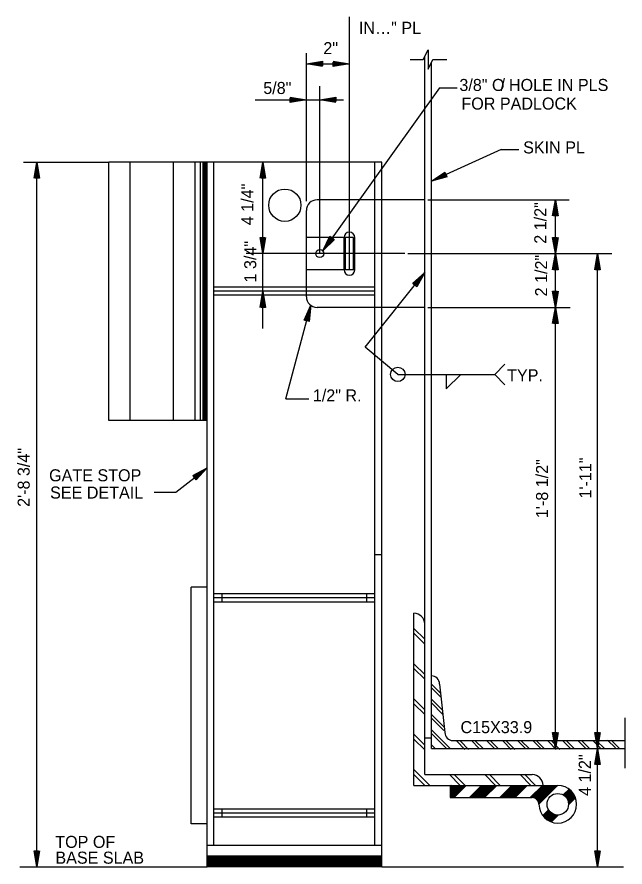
# Model space of a CAD drawing. Extents: x 0.1 to 13.5, y 0.1 to 9.5.
# Drawn here: x 6.55 to 8.905, y 3.832 to 7.124 of the extents above; entities that cross this region are included whole.
import ezdxf

# ---------------------------------------------------------------- set-up
doc = ezdxf.new("R2010")
doc.units = 0
for name, color, linetype in [('Level 13', 7, 'Continuous'), ('Level 25', 7, 'Continuous'), ('Level 36', 7, 'Continuous'), ('Level 44', 7, 'Continuous'), ('Level 50', 7, 'Continuous')]:
    doc.layers.add(name, color=color, linetype=linetype)

msp = doc.modelspace()

# ---------------------------------------------------------------- linework, layer by layer
at = {"layer": 'Level 13'}
for p, q in [((8.2281, 4.1483), (8.2281, 4.1014)), ((8.2281, 4.1483), (8.6448, 4.1483)), ((8.2685, 4.1483), (8.2281, 4.1079)), ((8.2611, 4.1483), (8.2281, 4.1153)), ((8.2537, 4.1483), (8.2281, 4.1226)), ((8.2464, 4.1483), (8.2281, 4.13)), ((8.239, 4.1483), (8.2281, 4.1374)), ((8.2353, 4.1483), (8.2281, 4.1411)), ((8.2427, 4.1483), (8.2281, 4.1337)), ((8.2316, 4.1483), (8.2281, 4.1448)), ((8.2501, 4.1483), (8.2281, 4.1263)), ((8.2574, 4.1483), (8.2281, 4.119)), ((8.2648, 4.1483), (8.2281, 4.1116)), ((8.2722, 4.1483), (8.2281, 4.1042)), ((8.2758, 4.1483), (8.229, 4.1014)), ((8.2795, 4.1483), (8.2327, 4.1014)), ((8.2832, 4.1483), (8.2363, 4.1014)), ((8.2869, 4.1483), (8.24, 4.1014)), ((8.2906, 4.1483), (8.2437, 4.1014)), ((8.3495, 4.1483), (8.3026, 4.1014)), ((8.3532, 4.1483), (8.3063, 4.1014)), ((8.3568, 4.1483), (8.31, 4.1014)), ((8.3605, 4.1483), (8.3137, 4.1014)), ((8.3642, 4.1483), (8.3173, 4.1014)), ((8.3679, 4.1483), (8.321, 4.1014)), ((8.3716, 4.1483), (8.3247, 4.1014)), ((8.3753, 4.1483), (8.3284, 4.1014)), ((8.3789, 4.1483), (8.3321, 4.1014)), ((8.3826, 4.1483), (8.3357, 4.1014)), ((8.3863, 4.1483), (8.3394, 4.1014)), ((8.39, 4.1483), (8.3431, 4.1014)), ((8.3937, 4.1483), (8.3468, 4.1014)), ((8.3973, 4.1483), (8.3505, 4.1014)), ((8.401, 4.1483), (8.3542, 4.1014)), ((8.4047, 4.1483), (8.3578, 4.1014)), ((8.4084, 4.1483), (8.3615, 4.1014)), ((8.4673, 4.1483), (8.4205, 4.1014)), ((8.471, 4.1483), (8.4241, 4.1014)), ((8.4747, 4.1483), (8.4278, 4.1014)), ((8.4784, 4.1483), (8.4315, 4.1014)), ((8.4821, 4.1483), (8.4352, 4.1014)), ((8.4857, 4.1483), (8.4389, 4.1014)), ((8.4894, 4.1483), (8.4426, 4.1014)), ((8.4931, 4.1483), (8.4462, 4.1014)), ((8.4968, 4.1483), (8.4499, 4.1014)), ((8.5005, 4.1483), (8.4536, 4.1014)), ((8.5042, 4.1483), (8.4573, 4.1014)), ((8.5078, 4.1483), (8.461, 4.1014)), ((8.5115, 4.1483), (8.4647, 4.1014)), ((8.5152, 4.1483), (8.4683, 4.1014)), ((8.5115, 4.1483), (8.4683, 4.1051)), ((8.5189, 4.1483), (8.472, 4.1014)), ((8.5226, 4.1483), (8.4757, 4.1014)), ((8.5263, 4.1483), (8.4794, 4.1014)), ((8.5852, 4.1483), (8.5383, 4.1014)), ((8.5889, 4.1483), (8.542, 4.1014)), ((8.5925, 4.1483), (8.5457, 4.1014)), ((8.5962, 4.1483), (8.5491, 4.1012)), ((8.5999, 4.1483), (8.5523, 4.1006)), ((8.6036, 4.1483), (8.5551, 4.0997)), ((8.6073, 4.1483), (8.5576, 4.0986)), ((8.611, 4.1483), (8.5599, 4.0972)), ((8.6146, 4.1483), (8.5621, 4.0957)), ((8.6183, 4.1483), (8.5639, 4.0939)), ((8.622, 4.1483), (8.5658, 4.0921)), ((8.6257, 4.1483), (8.5677, 4.0902)), ((8.6294, 4.1483), (8.5688, 4.0877)), ((8.6331, 4.1483), (8.57, 4.0852)), ((8.6367, 4.1483), (8.5709, 4.0824)), ((8.6404, 4.1483), (8.5716, 4.0794)), ((8.6441, 4.1483), (8.5719, 4.076)), ((8.6885, 4.1337), (8.666, 4.1112)), ((8.6906, 4.1321), (8.6683, 4.1098)), ((8.6926, 4.1304), (8.6704, 4.1082)), ((8.6944, 4.1286), (8.6724, 4.1066)), ((8.6964, 4.1269), (8.6743, 4.1048)), ((8.6982, 4.125), (8.6761, 4.1029)), ((8.6999, 4.1231), (8.6777, 4.1009)), ((8.7016, 4.1211), (8.6796, 4.099)), ((8.7032, 4.119), (8.6807, 4.0965)), ((8.7048, 4.1168), (8.682, 4.0941)), ((8.7062, 4.1146), (8.6832, 4.0916)), ((8.2281, 4.1014), (8.5458, 4.1014)), ((8.7076, 4.1124), (8.6842, 4.0889)), ((8.709, 4.11), (8.6851, 4.0861)), ((8.7102, 4.1076), (8.6858, 4.0831)), ((8.7114, 4.1051), (8.6862, 4.0799)), ((8.7135, 4.0998), (8.6864, 4.0727)), ((8.7125, 4.1025), (8.6865, 4.0765)), ((8.6089, 4.0542), (8.5864, 4.0317)), ((8.6104, 4.0519), (8.5883, 4.0298)), ((8.6119, 4.0498), (8.5897, 4.0276)), ((8.6136, 4.0478), (8.5916, 4.0257)), ((8.6154, 4.0459), (8.5933, 4.0238)), ((8.6172, 4.044), (8.5951, 4.0219)), ((8.6193, 4.0424), (8.5971, 4.0202)), ((8.6214, 4.0409), (8.5991, 4.0185)), ((8.6237, 4.0394), (8.6012, 4.0169)), ((8.6261, 4.0381), (8.6033, 4.0154)), ((8.6286, 4.037), (8.6055, 4.0139)), ((8.6312, 4.0359), (8.6078, 4.0125)), ((8.634, 4.0351), (8.6101, 4.0112)), ((8.637, 4.0344), (8.6126, 4.0099)), ((8.6402, 4.0339), (8.6151, 4.0088)), ((8.6437, 4.0337), (8.6177, 4.0077)), ((8.6474, 4.0338), (8.6203, 4.0066))]:
    msp.add_line(p, q, dxfattribs=at)
msp.add_lwpolyline([(8.124, 6.9584), (8.1426, 6.9959), (8.1426, 6.921), (8.1614, 6.9584)], dxfattribs=at)
msp.add_circle((8.6448, 4.0753), 0.0417, dxfattribs=at)
for centre, radius, start in [((8.6448, 4.0753), 0.0729, 180), ((8.5459, 4.0753), 0.026, 0)]:
    msp.add_arc(centre, radius, start, 90, dxfattribs=at)
at = {"layer": 'Level 25'}
for p, q in [((7.8377, 6.1449), (7.8377, 7.1236)), ((7.6711, 6.4099), (7.6711, 6.9833)), ((8.0737, 6.9584), (8.124, 6.9584)), ((8.1294, 4.1899), (8.1294, 6.9692)), ((8.1554, 4.3326), (8.1554, 6.9465)), ((8.1614, 6.9584), (8.2147, 6.9584)), ((7.6711, 6.9417), (7.8377, 6.9417)), ((7.7231, 6.2074), (7.7231, 6.8564)), ((8.187, 6.8498), (7.7347, 6.2179)), ((8.187, 6.8498), (8.2546, 6.8498)), ((7.4724, 6.8035), (7.6711, 6.8035)), ((7.6711, 6.8035), (7.7231, 6.8035)), ((7.7231, 6.8035), (7.815, 6.8035)), ((8.4259, 6.6108), (8.4935, 6.6108)), ((6.5752, 6.5615), (6.9054, 6.5615)), ((6.6265, 3.8324), (6.6265, 6.5615)), ((7.9627, 6.5615), (6.9054, 6.5615)), ((6.9054, 5.5615), (6.9054, 6.5615)), ((6.9888, 5.5615), (6.9888, 6.5615)), ((7.1567, 5.5615), (7.1567, 6.5615)), ((7.24, 5.5615), (7.24, 6.5615)), ((7.2608, 5.5615), (7.2608, 6.5615)), ((7.2713, 5.5615), (7.2713, 6.5615)), ((7.2765, 5.5615), (7.2765, 6.5615)), ((7.2817, 5.5615), (7.2817, 6.5615)), ((7.2869, 3.8324), (7.2869, 6.5615)), ((7.3131, 3.9157), (7.3131, 6.5615)), ((7.5028, 6.2074), (7.5028, 6.5615)), ((7.9365, 6.4157), (7.9365, 6.5615)), ((7.9627, 6.5615), (7.9627, 6.5615)), ((7.9627, 6.4157), (7.9627, 6.5615)), ((8.1294, 6.4157), (7.7127, 6.4157)), ((7.9365, 5.999), (7.9365, 6.4157)), ((7.9627, 5.999), (7.9627, 6.4157)), ((8.1413, 6.4157), (8.6889, 6.4157)), ((8.6354, 6.2074), (8.6354, 6.4157)), ((7.6711, 6.0407), (7.6711, 6.374)), ((7.8533, 6.2699), (7.6711, 6.2699)), ((7.8169, 6.1449), (7.8169, 6.2699)), ((7.8221, 6.1449), (7.8221, 6.2699)), ((7.8533, 6.1449), (7.8533, 6.2699)), ((7.8586, 6.1449), (7.8586, 6.2699)), ((8.0528, 6.2074), (7.4375, 6.2074)), ((7.5028, 6.0615), (7.5028, 6.2074)), ((8.0644, 6.2074), (8.8544, 6.2074)), ((8.6354, 5.999), (8.6354, 6.2074)), ((8.7985, 4.2909), (8.7985, 6.2074)), ((7.8533, 6.1449), (7.6711, 6.1449)), ((7.8993, 5.8454), (8.1294, 6.1346)), ((7.6711, 6.0771), (7.3131, 6.0771)), ((7.9365, 6.0615), (7.3131, 6.0615)), ((7.5028, 5.9169), (7.5028, 6.0615)), ((7.9365, 6.0771), (7.6711, 6.0771)), ((7.6711, 6.0459), (7.3131, 6.0459)), ((7.9365, 6.0459), (7.6711, 6.0459)), ((7.5917, 5.6446), (7.6879, 6.0072)), ((8.1294, 5.999), (7.7127, 5.999)), ((7.9365, 3.9157), (7.9365, 5.999)), ((7.9627, 3.8324), (7.9627, 5.999)), ((8.1413, 5.999), (8.6933, 5.999)), ((8.6354, 4.2909), (8.6354, 5.999)), ((8.0253, 5.7397), (7.8993, 5.8454)), ((8.4004, 5.7397), (8.4403, 5.7795)), ((8.0253, 5.7397), (8.4004, 5.7397)), ((8.2128, 5.7397), (8.2128, 5.6834)), ((8.2128, 5.6834), (8.2687, 5.7393)), ((8.4004, 5.7397), (8.4403, 5.6999)), ((7.5917, 5.6446), (7.6801, 5.6446)), ((7.2869, 5.5615), (6.9054, 5.5615)), ((7.1657, 5.2836), (7.2869, 5.3783)), ((7.081, 5.2836), (7.1657, 5.2836)), ((7.9627, 5.0407), (7.9365, 5.0407)), ((7.2244, 3.999), (7.2244, 4.9157)), ((7.2869, 4.9157), (7.2244, 4.9157)), ((7.9365, 4.8896), (7.3131, 4.8896)), ((7.9365, 4.874), (7.3131, 4.874)), ((7.9365, 4.874), (7.3131, 4.874)), ((7.3444, 4.8584), (7.3444, 4.8896)), ((7.9052, 4.8584), (7.9052, 4.8896)), ((7.9365, 4.8584), (7.3131, 4.8584)), ((8.0877, 4.1483), (8.0877, 4.8149)), ((8.1554, 4.2909), (8.1554, 4.5721)), ((8.1906, 4.5053), (8.1554, 4.5405)), ((8.1924, 4.4896), (8.1554, 4.5266)), ((8.1867, 4.5409), (8.2075, 4.3534)), ((8.198, 4.439), (8.1554, 4.4816)), ((8.1997, 4.4234), (8.1554, 4.4677)), ((8.2029, 4.3751), (8.1554, 4.4226)), ((8.9052, 4.2153), (8.9052, 4.4104)), ((8.2029, 4.3613), (8.1554, 4.4088)), ((8.2282, 4.2909), (8.1554, 4.3637)), ((8.2144, 4.2909), (8.1554, 4.3498)), ((8.1294, 4.3326), (8.1554, 4.3326)), ((8.2388, 4.3221), (8.9052, 4.3221)), ((8.2853, 4.2879), (8.2541, 4.3192)), ((8.2992, 4.2879), (8.268, 4.3192)), ((8.3409, 4.2913), (8.31, 4.3221)), ((8.3552, 4.2909), (8.3249, 4.3212)), ((8.3998, 4.2913), (8.3702, 4.3209)), ((8.4137, 4.2913), (8.3828, 4.3221)), ((8.4641, 4.2879), (8.4328, 4.3192)), ((8.478, 4.2879), (8.4467, 4.3192)), ((8.5196, 4.2913), (8.4888, 4.3221)), ((8.5339, 4.2909), (8.5036, 4.3212)), ((8.5786, 4.2913), (8.549, 4.3209)), ((8.5924, 4.2913), (8.5616, 4.3221)), ((8.6389, 4.2879), (8.6076, 4.3192)), ((8.6527, 4.2879), (8.6215, 4.3192)), ((8.6944, 4.2913), (8.6635, 4.3221)), ((8.7087, 4.2909), (8.6784, 4.3212)), ((8.7533, 4.2913), (8.7238, 4.3209)), ((8.7672, 4.2913), (8.7364, 4.3221)), ((8.8126, 4.2899), (8.7814, 4.3212)), ((8.8265, 4.2899), (8.7953, 4.3212)), ((8.8682, 4.2933), (8.8373, 4.3241)), ((8.8824, 4.2929), (8.8522, 4.3232)), ((8.1693, 4.2909), (8.1554, 4.3048)), ((8.1554, 4.2909), (8.1554, 4.2909)), ((8.1554, 4.2909), (8.696, 4.2909)), ((8.1554, 4.2909), (8.9052, 4.2909)), ((8.7985, 3.8324), (8.7985, 4.2909)), ((8.1294, 4.1899), (8.5461, 4.1899)), ((8.0877, 4.1483), (8.2281, 4.1483)), ((7.9365, 4.0563), (7.3131, 4.0563)), ((7.3444, 4.0251), (7.3444, 4.0563)), ((7.9052, 4.0251), (7.9052, 4.0563)), ((7.9365, 4.0407), (7.3131, 4.0407)), ((7.9365, 4.0251), (7.3131, 4.0251)), ((7.2869, 3.999), (7.2244, 3.999)), ((7.9627, 3.9157), (7.2869, 3.9157)), ((7.9627, 3.874), (7.2869, 3.874)), ((7.9627, 3.8688), (7.2869, 3.8688)), ((7.9627, 3.8636), (7.2869, 3.8636)), ((7.9627, 3.8584), (7.2869, 3.8584)), ((7.9627, 3.8532), (7.2869, 3.8532)), ((6.5612, 3.8324), (7.2869, 3.8324)), ((7.9627, 3.848), (7.2869, 3.848)), ((7.9627, 3.8428), (7.2869, 3.8428)), ((7.9627, 3.8376), (7.2869, 3.8376)), ((7.9627, 3.8324), (7.2869, 3.8324)), ((7.9627, 3.8324), (8.8996, 3.8324))]:
    msp.add_line(p, q, dxfattribs=at)
for centre, radius in [((7.5877, 6.3949), 0.0625), ((7.7231, 6.2074), 0.0156), ((8.0253, 5.7397), 0.0281)]:
    msp.add_circle(centre, radius, dxfattribs=at)
for centre, radius, start, end in [((7.7127, 6.374), 0.0417, 90, 180), ((7.8377, 6.2699), 0.0208, 0, 180), ((7.8377, 6.1449), 0.0208, 180, 357.4819), ((7.7127, 6.0407), 0.0417, 180, 270), ((8.0877, 4.7733), 0.0417, 0, 90), ((8.1554, 4.5409), 0.0313, 0, 90), ((8.2388, 4.3534), 0.0313, 180, 270), ((8.5461, 4.1483), 0.0417, 0, 90)]:
    msp.add_arc(centre, radius, start, end, dxfattribs=at)
at = {"layer": 'Level 36'}
msp.add_line((8.1554, 4.2909), (8.1554, 4.9155), dxfattribs=at)
at = {"layer": 'Level 44'}
for p, q in [((8.4259, 6.6108), (8.1554, 6.4877)), ((8.1294, 4.7146), (8.0877, 4.7563)), ((8.1294, 4.6958), (8.0877, 4.7374)), ((8.1294, 4.5779), (8.0877, 4.6196)), ((8.1294, 4.5591), (8.0877, 4.6007)), ((8.1294, 4.4412), (8.0877, 4.4829)), ((8.1294, 4.4224), (8.0877, 4.464)), ((8.1294, 4.3045), (8.0877, 4.3462)), ((8.1294, 4.2857), (8.0877, 4.3273)), ((8.1489, 4.1483), (8.0877, 4.2095)), ((8.1301, 4.1483), (8.0877, 4.1906)), ((8.2668, 4.1483), (8.2251, 4.1899)), ((8.2856, 4.1483), (8.244, 4.1899)), ((8.4035, 4.1483), (8.3618, 4.1899)), ((8.4223, 4.1483), (8.3807, 4.1899)), ((8.5402, 4.1483), (8.4985, 4.1899)), ((8.5591, 4.1483), (8.5174, 4.1899))]:
    msp.add_line(p, q, dxfattribs=at)
at = {"layer": 'Level 50'}
for p, q in [((7.6711, 6.9417), (7.6711, 6.9417)), ((7.6884, 6.9417), (7.6884, 6.9417)), ((7.8204, 6.9417), (7.8204, 6.9417)), ((7.8377, 6.9417), (7.8377, 6.9417)), ((7.6537, 6.8035), (7.6537, 6.8035)), ((7.6711, 6.8035), (7.6711, 6.8035)), ((7.7231, 6.8035), (7.7231, 6.8035)), ((7.7405, 6.8035), (7.7405, 6.8035)), ((6.6265, 6.5615), (6.6265, 6.5615)), ((7.5028, 6.5615), (7.5028, 6.5615)), ((6.6265, 6.5442), (6.6265, 6.5442)), ((7.5028, 6.5442), (7.5028, 6.5442)), ((8.1554, 6.4877), (8.1554, 6.4877)), ((8.1712, 6.4949), (8.1712, 6.4949)), ((8.6354, 6.4157), (8.6354, 6.4157)), ((8.6354, 6.3984), (8.6354, 6.3984)), ((7.5028, 6.2247), (7.5028, 6.2247)), ((7.7448, 6.232), (7.7448, 6.232)), ((8.6354, 6.2247), (8.6354, 6.2247)), ((7.5028, 6.2074), (7.5028, 6.2074)), ((7.7347, 6.2179), (7.7347, 6.2179)), ((8.6354, 6.2074), (8.6354, 6.2074)), ((8.6354, 6.2074), (8.6354, 6.2074)), ((8.6354, 6.2074), (8.6354, 6.2074)), ((8.6354, 6.19), (8.6354, 6.19)), ((8.6354, 6.19), (8.6354, 6.19)), ((8.7985, 6.2074), (8.7985, 6.2074)), ((8.7985, 6.19), (8.7985, 6.19)), ((8.1294, 6.1346), (8.1294, 6.1346)), ((8.1186, 6.121), (8.1186, 6.121)), ((7.5028, 6.0615), (7.5028, 6.0615)), ((7.5028, 6.0442), (7.5028, 6.0442)), ((7.6835, 5.9904), (7.6835, 5.9904)), ((7.6879, 6.0072), (7.6879, 6.0072)), ((8.6354, 6.0164), (8.6354, 6.0164)), ((8.6354, 5.999), (8.6354, 5.999)), ((8.6354, 5.999), (8.6354, 5.999)), ((8.6354, 5.9817), (8.6354, 5.9817)), ((7.2732, 5.3677), (7.2732, 5.3677)), ((7.2869, 5.3783), (7.2869, 5.3783)), ((8.6354, 4.3082), (8.6354, 4.3082)), ((8.6354, 4.2909), (8.6354, 4.2909)), ((8.7985, 4.3082), (8.7985, 4.3082)), ((8.7985, 4.2909), (8.7985, 4.2909)), ((8.7985, 4.2909), (8.7985, 4.2909)), ((8.7985, 4.2736), (8.7985, 4.2736)), ((6.6265, 3.8497), (6.6265, 3.8497)), ((6.6265, 3.8324), (6.6265, 3.8324)), ((8.7985, 3.8497), (8.7985, 3.8497)), ((8.7985, 3.8324), (8.7985, 3.8324))]:
    msp.add_line(p, q, dxfattribs=at)
for points in [[(7.7334, 6.9314), (7.6711, 6.9417), (7.7334, 6.9521), (7.7334, 6.9344), (7.6884, 6.9417), (7.7307, 6.9487), (7.7307, 6.9374), (7.7051, 6.9417), (7.7281, 6.9454), (7.7281, 6.9407), (7.7224, 6.9417)], [(7.7754, 6.9521), (7.8377, 6.9417), (7.7754, 6.9314), (7.7754, 6.9491), (7.8204, 6.9417), (7.7781, 6.9347), (7.7781, 6.9461), (7.8037, 6.9417), (7.7807, 6.9381), (7.7807, 6.9427), (7.7864, 6.9417)], [(7.6087, 6.8138), (7.6711, 6.8035), (7.6087, 6.7931), (7.6087, 6.8108), (7.6537, 6.8035), (7.6114, 6.7965), (7.6114, 6.8078), (7.6371, 6.8035), (7.6141, 6.7998), (7.6141, 6.8045), (7.6197, 6.8035)], [(7.7855, 6.7931), (7.7231, 6.8035), (7.7855, 6.8138), (7.7855, 6.7961), (7.7405, 6.8035), (7.7828, 6.8105), (7.7828, 6.7991), (7.7571, 6.8035), (7.7801, 6.8071), (7.7801, 6.8025), (7.7745, 6.8035)], [(6.6162, 6.4992), (6.6265, 6.5615), (6.6368, 6.4992), (6.6192, 6.4992), (6.6265, 6.5442), (6.6335, 6.5019), (6.6222, 6.5019), (6.6265, 6.5275), (6.6302, 6.5045), (6.6255, 6.5045), (6.6265, 6.5102)], [(7.4924, 6.4992), (7.5028, 6.5615), (7.5131, 6.4992), (7.4954, 6.4992), (7.5028, 6.5442), (7.5098, 6.5019), (7.4984, 6.5019), (7.5028, 6.5275), (7.5064, 6.5045), (7.5018, 6.5045), (7.5028, 6.5102)], [(8.2164, 6.5041), (8.1554, 6.4877), (8.2079, 6.5229), (8.2152, 6.5069), (8.1712, 6.4949), (8.2068, 6.5188), (8.2115, 6.5085), (8.1864, 6.5018), (8.2058, 6.5147), (8.2077, 6.5104), (8.2021, 6.509)], [(8.625, 6.3534), (8.6354, 6.4157), (8.6457, 6.3534), (8.628, 6.3534), (8.6354, 6.3984), (8.6424, 6.356), (8.631, 6.356), (8.6354, 6.3817), (8.639, 6.3587), (8.6344, 6.3587), (8.6354, 6.3644)], [(7.5131, 6.2697), (7.5028, 6.2074), (7.4924, 6.2697), (7.5101, 6.2697), (7.5028, 6.2247), (7.4958, 6.267), (7.5071, 6.267), (7.5028, 6.2414), (7.4991, 6.2644), (7.5038, 6.2644), (7.5028, 6.2587)], [(7.7794, 6.2626), (7.7347, 6.2179), (7.7625, 6.2746), (7.7769, 6.2643), (7.7448, 6.232), (7.7637, 6.2705), (7.7729, 6.2639), (7.7545, 6.2455), (7.7649, 6.2664), (7.7687, 6.2637), (7.7645, 6.2596)], [(8.6457, 6.2697), (8.6354, 6.2074), (8.625, 6.2697), (8.6427, 6.2697), (8.6354, 6.2247), (8.6284, 6.267), (8.6397, 6.267), (8.6354, 6.2414), (8.6317, 6.2644), (8.6364, 6.2644), (8.6354, 6.2587)], [(8.625, 6.145), (8.6354, 6.2074), (8.6457, 6.145), (8.628, 6.145), (8.6354, 6.19), (8.6424, 6.1477), (8.631, 6.1477), (8.6354, 6.1734), (8.639, 6.1504), (8.6344, 6.1504), (8.6354, 6.156)], [(8.625, 6.145), (8.6354, 6.2074), (8.6457, 6.145), (8.628, 6.145), (8.6354, 6.19), (8.6424, 6.1477), (8.631, 6.1477), (8.6354, 6.1734), (8.639, 6.1504), (8.6344, 6.1504), (8.6354, 6.156)], [(8.7882, 6.145), (8.7985, 6.2074), (8.8088, 6.145), (8.7912, 6.145), (8.7985, 6.19), (8.8055, 6.1477), (8.7942, 6.1477), (8.7985, 6.1734), (8.8022, 6.1504), (8.7975, 6.1504), (8.7985, 6.156)], [(8.0825, 6.0922), (8.1294, 6.1346), (8.0987, 6.0794), (8.0848, 6.0904), (8.1186, 6.121), (8.0977, 6.0835), (8.0888, 6.0906), (8.1082, 6.108), (8.0968, 6.0877), (8.0931, 6.0906), (8.0974, 6.0944)], [(7.4924, 5.9992), (7.5028, 6.0615), (7.5131, 5.9992), (7.4954, 5.9992), (7.5028, 6.0442), (7.5098, 6.0019), (7.4984, 6.0019), (7.5028, 6.0275), (7.5064, 6.0045), (7.5018, 6.0045), (7.5028, 6.0102)], [(8.6457, 6.0614), (8.6354, 5.999), (8.625, 6.0614), (8.6427, 6.0614), (8.6354, 6.0164), (8.6284, 6.0587), (8.6397, 6.0587), (8.6354, 6.033), (8.6317, 6.056), (8.6364, 6.056), (8.6354, 6.0504)], [(7.662, 5.9496), (7.6879, 6.0072), (7.6819, 5.9443), (7.6649, 5.9488), (7.6835, 5.9904), (7.6794, 5.9477), (7.6684, 5.9506), (7.6792, 5.9743), (7.6769, 5.9512), (7.6724, 5.9524), (7.6748, 5.9576)], [(8.625, 5.9367), (8.6354, 5.999), (8.6457, 5.9367), (8.628, 5.9367), (8.6354, 5.9817), (8.6424, 5.9394), (8.631, 5.9394), (8.6354, 5.965), (8.639, 5.942), (8.6344, 5.942), (8.6354, 5.9477)], [(7.2314, 5.3481), (7.2869, 5.3783), (7.2441, 5.3318), (7.2333, 5.3457), (7.2732, 5.3677), (7.2442, 5.3361), (7.2372, 5.345), (7.2601, 5.3574), (7.2442, 5.3403), (7.2414, 5.344), (7.2464, 5.3467)], [(8.6457, 4.3532), (8.6354, 4.2909), (8.625, 4.3532), (8.6427, 4.3532), (8.6354, 4.3082), (8.6284, 4.3506), (8.6397, 4.3506), (8.6354, 4.3249), (8.6317, 4.3479), (8.6364, 4.3479), (8.6354, 4.3422)], [(8.8088, 4.3532), (8.7985, 4.2909), (8.7882, 4.3532), (8.8058, 4.3532), (8.7985, 4.3082), (8.7915, 4.3506), (8.8028, 4.3506), (8.7985, 4.3249), (8.7948, 4.3479), (8.7995, 4.3479), (8.7985, 4.3422)], [(8.7882, 4.2286), (8.7985, 4.2909), (8.8088, 4.2286), (8.7912, 4.2286), (8.7985, 4.2736), (8.8055, 4.2312), (8.7942, 4.2312), (8.7985, 4.2569), (8.8022, 4.2339), (8.7975, 4.2339), (8.7985, 4.2396)], [(6.6368, 3.8947), (6.6265, 3.8324), (6.6162, 3.8947), (6.6338, 3.8947), (6.6265, 3.8497), (6.6195, 3.892), (6.6308, 3.892), (6.6265, 3.8664), (6.6228, 3.8894), (6.6275, 3.8894), (6.6265, 3.8837)], [(8.8088, 3.8947), (8.7985, 3.8324), (8.7882, 3.8947), (8.8058, 3.8947), (8.7985, 3.8497), (8.7915, 3.892), (8.8028, 3.892), (8.7985, 3.8664), (8.7948, 3.8894), (8.7995, 3.8894), (8.7985, 3.8837)]]:
    msp.add_lwpolyline(points, dxfattribs=at)

# ---------------------------------------------------------------- texts
at = {"layer": 'Level 25'}
for s, height, p in [('IN…" PL', 0.04667, (7.8746, 7.0584)), ('2"', 0.04667, (7.7368, 6.9797)), ('3/8" O HOLE IN PLS', 0.046667, (8.2637, 6.8371)), ('/', 0.0467, (8.4232, 6.8382)), ('5/8"', 0.04667, (7.5041, 6.8254)), ('FOR PADLOCK', 0.046667, (8.2715, 6.765)), ('SKIN PL', 0.04667, (8.5108, 6.5953)), ('TYP.', 0.04667, (8.4486, 5.7129)), ('1/2" R.', 0.04667, (7.6961, 5.6349)), ('GATE STOP', 0.04667, (6.6746, 5.3257)), ('SEE DETAIL', 0.04667, (6.6784, 5.2589)), ('C15X33.9', 0.04667, (8.2681, 4.3506)), ('TOP OF', 0.04667, (6.6985, 3.9063)), ('BASE SLAB', 0.04667, (6.699, 3.8451))]:
    msp.add_text(s, height=height, dxfattribs=at).set_placement(p)
for s, p in [('4 1/4"', (7.4657, 6.3173)), ('2 1/2"', (8.6005, 6.2457)), ('1 3/4"', (7.477, 6.0957)), ('2 1/2"', (8.6037, 6.0417)), ('2\'-8 3/4"', (6.5994, 5.2266)), ('1\'-8 1/2"', (8.6072, 5.1832)), ('1\'-11"', (8.7751, 5.259)), ('4 1/2"', (8.7729, 4.1076))]:
    msp.add_text(s, height=0.04667, rotation=90, dxfattribs=at).set_placement(p)

doc.saveas('drawing.dxf')
